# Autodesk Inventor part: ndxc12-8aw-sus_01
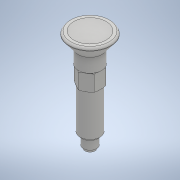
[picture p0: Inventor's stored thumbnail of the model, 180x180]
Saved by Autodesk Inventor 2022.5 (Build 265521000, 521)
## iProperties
Part Number: ndxc12-8aw-sus_01
Material: 一般
Document SubType Name: Modeling
Designer: ImaoCorp
Density: 1 g/cm^3
Appearance: 既定
Author: ImaoCorp
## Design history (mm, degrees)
feature "ndxc12-8aw-sus_01"
node "ソリッド1"
